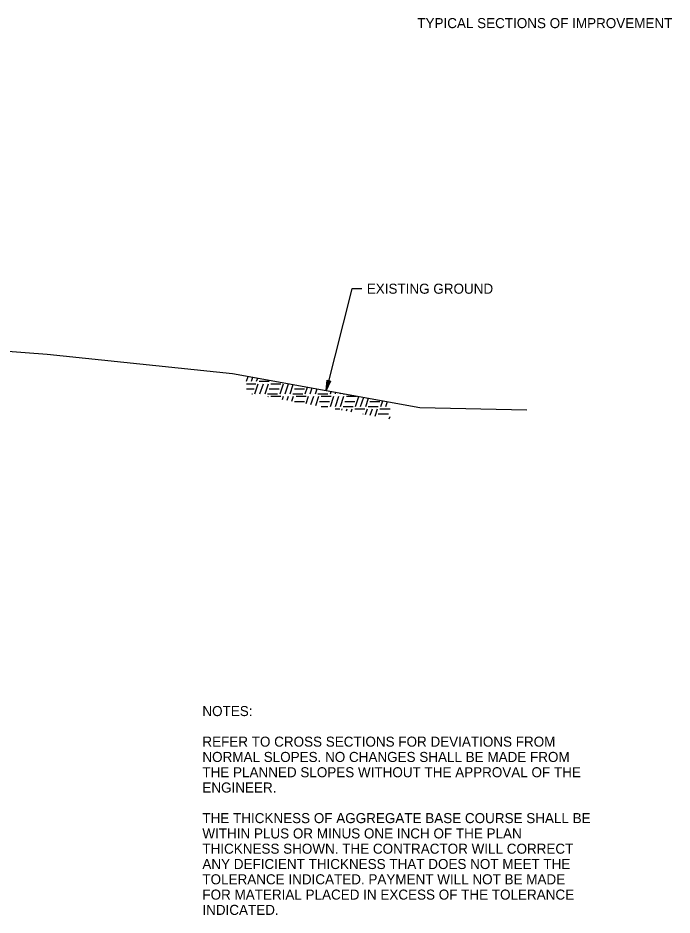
# Model space of a CAD drawing. Extents: x 1824008 to 1828864, y 689441 to 689870.
# Drawn here: x 1828825.4 to 1828864.4, y 689656.7 to 689710.2 of the extents above; entities that cross this region are included whole.
import ezdxf

# ---------------------------------------------------------------- set-up
doc = ezdxf.new("R2010")
doc.units = 0
for name, color, linetype in [('1', 7, 'Continuous'), ('19', 7, 'Continuous'), ('R_Draft', 7, 'Continuous')]:
    doc.layers.add(name, color=color, linetype=linetype)

msp = doc.modelspace()

# ---------------------------------------------------------------- linework, layer by layer
at = {"layer": '1'}
for p, q in [((1828839.043, 689688.541), (1828839.136, 689688.823)), ((1828839.043, 689688.541), (1828839.136, 689688.823)), ((1828839.043, 689688.541), (1828839.136, 689688.823)), ((1828839.34, 689688.532), (1828839.419, 689688.771)), ((1828839.34, 689688.532), (1828839.419, 689688.771)), ((1828839.34, 689688.532), (1828839.419, 689688.771)), ((1828839.64, 689688.532), (1828839.702, 689688.72)), ((1828839.64, 689688.532), (1828839.702, 689688.72)), ((1828839.64, 689688.532), (1828839.702, 689688.72)), ((1828839.043, 689688.382), (1828839.54, 689688.382)), ((1828839.043, 689688.382), (1828839.54, 689688.382)), ((1828839.043, 689688.382), (1828839.54, 689688.382)), ((1828839.043, 689688.082), (1828839.49, 689688.082)), ((1828839.043, 689688.082), (1828839.49, 689688.082)), ((1828839.043, 689688.082), (1828839.49, 689688.082)), ((1828839.54, 689687.782), (1828839.74, 689688.382)), ((1828839.54, 689688.382), (1828839.59, 689688.382)), ((1828839.54, 689687.782), (1828839.74, 689688.382)), ((1828839.54, 689688.382), (1828839.59, 689688.382)), ((1828839.54, 689687.782), (1828839.74, 689688.382)), ((1828839.54, 689688.382), (1828839.59, 689688.382)), ((1828839.79, 689688.532), (1828840.39, 689688.532)), ((1828839.79, 689688.532), (1828840.39, 689688.532)), ((1828839.79, 689688.532), (1828840.39, 689688.532)), ((1828839.84, 689687.782), (1828840.04, 689688.382)), ((1828839.84, 689687.782), (1828840.04, 689688.382)), ((1828839.84, 689687.782), (1828840.04, 689688.382)), ((1828840.14, 689687.782), (1828840.34, 689688.382)), ((1828840.14, 689687.782), (1828840.34, 689688.382)), ((1828840.14, 689687.782), (1828840.34, 689688.382)), ((1828840.39, 689688.082), (1828840.99, 689688.082)), ((1828840.39, 689688.082), (1828840.99, 689688.082)), ((1828840.39, 689688.082), (1828840.99, 689688.082)), ((1828840.49, 689688.382), (1828841.09, 689688.382)), ((1828840.49, 689688.382), (1828841.09, 689688.382)), ((1828840.49, 689688.382), (1828841.09, 689688.382)), ((1828840.54, 689688.532), (1828840.551, 689688.566)), ((1828840.54, 689688.532), (1828840.551, 689688.566)), ((1828840.54, 689688.532), (1828840.551, 689688.566)), ((1828841.04, 689687.782), (1828841.24, 689688.382)), ((1828841.04, 689687.782), (1828841.24, 689688.382)), ((1828841.04, 689687.782), (1828841.24, 689688.382)), ((1828841.34, 689687.782), (1828841.54, 689688.382)), ((1828841.34, 689687.782), (1828841.54, 689688.382)), ((1828841.34, 689687.782), (1828841.54, 689688.382)), ((1828841.64, 689687.782), (1828841.824, 689688.335)), ((1828841.64, 689687.782), (1828841.824, 689688.335)), ((1828841.64, 689687.782), (1828841.824, 689688.335)), ((1828841.89, 689688.082), (1828842.49, 689688.082)), ((1828841.89, 689688.082), (1828842.49, 689688.082)), ((1828841.89, 689688.082), (1828842.49, 689688.082)), ((1828842.54, 689687.782), (1828842.673, 689688.181)), ((1828842.54, 689687.782), (1828842.673, 689688.181)), ((1828842.54, 689687.782), (1828842.673, 689688.181)), ((1828842.84, 689687.782), (1828842.956, 689688.13)), ((1828842.84, 689687.782), (1828842.956, 689688.13)), ((1828842.84, 689687.782), (1828842.956, 689688.13)), ((1828843.14, 689687.782), (1828843.238, 689688.079)), ((1828843.14, 689687.782), (1828843.238, 689688.079)), ((1828843.14, 689687.782), (1828843.238, 689688.079)), ((1828843.792, 689687.978), (1828843.835, 689688.586)), ((1828844.038, 689688.535), (1828843.792, 689687.978)), ((1828843.82, 689688.135), (1828843.886, 689688.568)), ((1828843.835, 689688.586), (1828844.038, 689688.535)), ((1828843.992, 689688.543), (1828843.845, 689688.131)), ((1828839.357, 689687.782), (1828839.39, 689687.782)), ((1828839.357, 689687.782), (1828839.39, 689687.782)), ((1828839.357, 689687.782), (1828839.39, 689687.782)), ((1828840.29, 689687.782), (1828840.89, 689687.782)), ((1828840.29, 689687.782), (1828840.89, 689687.782)), ((1828840.29, 689687.782), (1828840.89, 689687.782)), ((1828840.331, 689687.606), (1828840.34, 689687.632)), ((1828840.331, 689687.606), (1828840.34, 689687.632)), ((1828840.331, 689687.606), (1828840.34, 689687.632)), ((1828840.49, 689687.632), (1828841.09, 689687.632)), ((1828840.49, 689687.632), (1828841.09, 689687.632)), ((1828840.49, 689687.632), (1828841.09, 689687.632)), ((1828841.18, 689687.452), (1828841.24, 689687.632)), ((1828841.18, 689687.452), (1828841.24, 689687.632)), ((1828841.18, 689687.452), (1828841.24, 689687.632)), ((1828841.462, 689687.401), (1828841.54, 689687.632)), ((1828841.462, 689687.401), (1828841.54, 689687.632)), ((1828841.462, 689687.401), (1828841.54, 689687.632)), ((1828841.745, 689687.35), (1828841.84, 689687.632)), ((1828841.745, 689687.35), (1828841.84, 689687.632)), ((1828841.745, 689687.35), (1828841.84, 689687.632)), ((1828841.79, 689687.782), (1828842.39, 689687.782)), ((1828841.79, 689687.782), (1828842.39, 689687.782)), ((1828841.79, 689687.782), (1828842.39, 689687.782)), ((1828841.99, 689687.632), (1828842.54, 689687.632)), ((1828841.99, 689687.632), (1828842.54, 689687.632)), ((1828841.99, 689687.632), (1828842.54, 689687.632)), ((1828842.54, 689687.632), (1828842.59, 689687.632)), ((1828842.54, 689687.632), (1828842.59, 689687.632)), ((1828842.54, 689687.632), (1828842.59, 689687.632)), ((1828842.594, 689687.196), (1828842.74, 689687.632)), ((1828842.594, 689687.196), (1828842.74, 689687.632)), ((1828842.594, 689687.196), (1828842.74, 689687.632)), ((1828842.877, 689687.144), (1828843.04, 689687.632)), ((1828842.877, 689687.144), (1828843.04, 689687.632)), ((1828842.877, 689687.144), (1828843.04, 689687.632)), ((1828843.16, 689687.093), (1828843.34, 689687.632)), ((1828843.16, 689687.093), (1828843.34, 689687.632)), ((1828843.16, 689687.093), (1828843.34, 689687.632)), ((1828843.29, 689687.782), (1828843.89, 689687.782)), ((1828843.29, 689687.782), (1828843.89, 689687.782)), ((1828843.29, 689687.782), (1828843.89, 689687.782)), ((1828843.49, 689687.632), (1828844.09, 689687.632)), ((1828843.49, 689687.632), (1828844.09, 689687.632)), ((1828843.49, 689687.632), (1828844.09, 689687.632)), ((1828844.04, 689687.782), (1828844.087, 689687.925)), ((1828844.04, 689687.782), (1828844.087, 689687.925)), ((1828844.04, 689687.782), (1828844.087, 689687.925)), ((1828844.04, 689687.032), (1828844.24, 689687.632)), ((1828844.04, 689687.032), (1828844.24, 689687.632)), ((1828844.04, 689687.032), (1828844.24, 689687.632)), ((1828844.34, 689687.782), (1828844.37, 689687.874)), ((1828844.34, 689687.782), (1828844.37, 689687.874)), ((1828844.34, 689687.782), (1828844.37, 689687.874)), ((1828844.34, 689687.032), (1828844.54, 689687.632)), ((1828844.34, 689687.032), (1828844.54, 689687.632)), ((1828844.34, 689687.032), (1828844.54, 689687.632)), ((1828844.64, 689687.782), (1828844.653, 689687.822)), ((1828844.64, 689687.782), (1828844.653, 689687.822)), ((1828844.64, 689687.782), (1828844.653, 689687.822)), ((1828844.64, 689687.032), (1828844.84, 689687.632)), ((1828844.64, 689687.032), (1828844.84, 689687.632)), ((1828844.64, 689687.032), (1828844.84, 689687.632)), ((1828844.79, 689687.782), (1828844.872, 689687.782)), ((1828844.79, 689687.782), (1828844.872, 689687.782)), ((1828844.79, 689687.782), (1828844.872, 689687.782)), ((1828844.99, 689687.632), (1828845.54, 689687.632)), ((1828844.99, 689687.632), (1828845.54, 689687.632)), ((1828844.99, 689687.632), (1828845.54, 689687.632)), ((1828845.54, 689687.632), (1828845.59, 689687.632)), ((1828845.54, 689687.632), (1828845.59, 689687.632)), ((1828845.54, 689687.632), (1828845.59, 689687.632)), ((1828845.54, 689687.032), (1828845.737, 689687.626)), ((1828845.54, 689687.032), (1828845.737, 689687.626)), ((1828845.54, 689687.032), (1828845.737, 689687.626)), ((1828845.84, 689687.032), (1828846.02, 689687.574)), ((1828845.84, 689687.032), (1828846.02, 689687.574)), ((1828845.84, 689687.032), (1828846.02, 689687.574)), ((1828841.89, 689687.332), (1828842.49, 689687.332)), ((1828841.89, 689687.332), (1828842.49, 689687.332)), ((1828841.89, 689687.332), (1828842.49, 689687.332)), ((1828843.39, 689687.332), (1828843.99, 689687.332)), ((1828843.39, 689687.332), (1828843.99, 689687.332)), ((1828843.39, 689687.332), (1828843.99, 689687.332)), ((1828843.494, 689687.032), (1828843.89, 689687.032)), ((1828843.494, 689687.032), (1828843.89, 689687.032)), ((1828843.494, 689687.032), (1828843.89, 689687.032)), ((1828844.79, 689687.032), (1828845.39, 689687.032)), ((1828844.79, 689687.032), (1828845.39, 689687.032)), ((1828844.79, 689687.032), (1828845.39, 689687.032)), ((1828844.89, 689687.332), (1828845.49, 689687.332)), ((1828844.89, 689687.332), (1828845.49, 689687.332)), ((1828844.89, 689687.332), (1828845.49, 689687.332)), ((1828846.14, 689687.032), (1828846.303, 689687.523)), ((1828846.14, 689687.032), (1828846.303, 689687.523)), ((1828846.14, 689687.032), (1828846.303, 689687.523)), ((1828846.29, 689687.032), (1828846.89, 689687.032)), ((1828846.29, 689687.032), (1828846.89, 689687.032)), ((1828846.29, 689687.032), (1828846.89, 689687.032)), ((1828846.39, 689687.332), (1828846.99, 689687.332)), ((1828846.39, 689687.332), (1828846.99, 689687.332)), ((1828846.39, 689687.332), (1828846.99, 689687.332)), ((1828847.04, 689687.032), (1828847.152, 689687.369)), ((1828847.04, 689687.032), (1828847.152, 689687.369)), ((1828847.04, 689687.032), (1828847.152, 689687.369)), ((1828847.34, 689687.032), (1828847.435, 689687.318)), ((1828847.34, 689687.032), (1828847.435, 689687.318)), ((1828847.34, 689687.032), (1828847.435, 689687.318)), ((1828844.321, 689686.882), (1828844.59, 689686.882)), ((1828844.321, 689686.882), (1828844.59, 689686.882)), ((1828844.321, 689686.882), (1828844.59, 689686.882)), ((1828844.716, 689686.811), (1828844.74, 689686.882)), ((1828844.716, 689686.811), (1828844.74, 689686.882)), ((1828844.716, 689686.811), (1828844.74, 689686.882)), ((1828844.999, 689686.76), (1828845.04, 689686.882)), ((1828844.999, 689686.76), (1828845.04, 689686.882)), ((1828844.999, 689686.76), (1828845.04, 689686.882)), ((1828845.282, 689686.708), (1828845.34, 689686.882)), ((1828845.282, 689686.708), (1828845.34, 689686.882)), ((1828845.282, 689686.708), (1828845.34, 689686.882)), ((1828845.49, 689686.882), (1828845.54, 689686.882)), ((1828845.49, 689686.882), (1828845.54, 689686.882)), ((1828845.49, 689686.882), (1828845.54, 689686.882)), ((1828845.54, 689686.882), (1828846.09, 689686.882)), ((1828845.54, 689686.882), (1828846.09, 689686.882)), ((1828845.54, 689686.882), (1828846.09, 689686.882)), ((1828845.975, 689686.582), (1828845.99, 689686.582)), ((1828845.975, 689686.582), (1828845.99, 689686.582)), ((1828845.975, 689686.582), (1828845.99, 689686.582)), ((1828846.13, 689686.554), (1828846.24, 689686.882)), ((1828846.13, 689686.554), (1828846.24, 689686.882)), ((1828846.13, 689686.554), (1828846.24, 689686.882)), ((1828846.413, 689686.503), (1828846.54, 689686.882)), ((1828846.413, 689686.503), (1828846.54, 689686.882)), ((1828846.413, 689686.503), (1828846.54, 689686.882)), ((1828846.696, 689686.452), (1828846.84, 689686.882)), ((1828846.696, 689686.452), (1828846.84, 689686.882)), ((1828846.696, 689686.452), (1828846.84, 689686.882)), ((1828846.89, 689686.582), (1828847.49, 689686.582)), ((1828846.89, 689686.582), (1828847.49, 689686.582)), ((1828846.89, 689686.582), (1828847.49, 689686.582)), ((1828846.99, 689686.882), (1828847.589, 689686.882)), ((1828846.99, 689686.882), (1828847.589, 689686.882)), ((1828846.99, 689686.882), (1828847.589, 689686.882)), ((1828847.545, 689686.298), (1828847.589, 689686.43)), ((1828847.545, 689686.298), (1828847.589, 689686.43)), ((1828847.545, 689686.298), (1828847.589, 689686.43))]:
    msp.add_line(p, q, dxfattribs=at)
for points in [[(1828845.904, 689694.052), (1828845.304, 689694.051), (1828843.792, 689687.978)], [(1828815.101, 689691.061), (1828827.154, 689690.152), (1828838.209, 689688.991), (1828849.374, 689686.966), (1828855.735, 689686.83)]]:
    msp.add_lwpolyline(points, dxfattribs=at)
at = {"layer": 'R_Draft'}
for p, q in [((1828839.043, 689688.541), (1828839.136, 689688.823)), ((1828839.34, 689688.532), (1828839.419, 689688.771)), ((1828839.64, 689688.532), (1828839.702, 689688.72)), ((1828839.043, 689688.382), (1828839.54, 689688.382)), ((1828839.043, 689688.082), (1828839.49, 689688.082)), ((1828839.54, 689687.782), (1828839.74, 689688.382)), ((1828839.54, 689688.382), (1828839.59, 689688.382)), ((1828839.79, 689688.532), (1828840.39, 689688.532)), ((1828839.84, 689687.782), (1828840.04, 689688.382)), ((1828840.14, 689687.782), (1828840.34, 689688.382)), ((1828840.39, 689688.082), (1828840.99, 689688.082)), ((1828840.49, 689688.382), (1828841.09, 689688.382)), ((1828840.54, 689688.532), (1828840.551, 689688.566)), ((1828841.04, 689687.782), (1828841.24, 689688.382)), ((1828841.34, 689687.782), (1828841.54, 689688.382)), ((1828841.64, 689687.782), (1828841.824, 689688.335)), ((1828841.89, 689688.082), (1828842.49, 689688.082)), ((1828842.54, 689687.782), (1828842.673, 689688.181)), ((1828842.84, 689687.782), (1828842.956, 689688.13)), ((1828843.14, 689687.782), (1828843.238, 689688.079)), ((1828839.357, 689687.782), (1828839.39, 689687.782)), ((1828840.29, 689687.782), (1828840.89, 689687.782)), ((1828840.331, 689687.606), (1828840.34, 689687.632)), ((1828840.49, 689687.632), (1828841.09, 689687.632)), ((1828841.18, 689687.452), (1828841.24, 689687.632)), ((1828841.462, 689687.401), (1828841.54, 689687.632)), ((1828841.745, 689687.35), (1828841.84, 689687.632)), ((1828841.79, 689687.782), (1828842.39, 689687.782)), ((1828841.99, 689687.632), (1828842.54, 689687.632)), ((1828842.54, 689687.632), (1828842.59, 689687.632)), ((1828842.594, 689687.196), (1828842.74, 689687.632)), ((1828842.877, 689687.144), (1828843.04, 689687.632)), ((1828843.16, 689687.093), (1828843.34, 689687.632)), ((1828843.29, 689687.782), (1828843.89, 689687.782)), ((1828843.49, 689687.632), (1828844.09, 689687.632)), ((1828844.04, 689687.782), (1828844.087, 689687.925)), ((1828844.04, 689687.032), (1828844.24, 689687.632)), ((1828844.34, 689687.782), (1828844.37, 689687.874)), ((1828844.34, 689687.032), (1828844.54, 689687.632)), ((1828844.64, 689687.782), (1828844.653, 689687.822)), ((1828844.64, 689687.032), (1828844.84, 689687.632)), ((1828844.79, 689687.782), (1828844.872, 689687.782)), ((1828844.99, 689687.632), (1828845.54, 689687.632)), ((1828845.54, 689687.632), (1828845.59, 689687.632)), ((1828845.54, 689687.032), (1828845.737, 689687.626)), ((1828845.84, 689687.032), (1828846.02, 689687.574)), ((1828841.89, 689687.332), (1828842.49, 689687.332)), ((1828843.39, 689687.332), (1828843.99, 689687.332)), ((1828843.494, 689687.032), (1828843.89, 689687.032)), ((1828844.79, 689687.032), (1828845.39, 689687.032)), ((1828844.89, 689687.332), (1828845.49, 689687.332)), ((1828846.14, 689687.032), (1828846.303, 689687.523)), ((1828846.29, 689687.032), (1828846.89, 689687.032)), ((1828846.39, 689687.332), (1828846.99, 689687.332)), ((1828847.04, 689687.032), (1828847.152, 689687.369)), ((1828847.34, 689687.032), (1828847.435, 689687.318)), ((1828844.321, 689686.882), (1828844.59, 689686.882)), ((1828844.716, 689686.811), (1828844.74, 689686.882)), ((1828844.999, 689686.76), (1828845.04, 689686.882)), ((1828845.282, 689686.708), (1828845.34, 689686.882)), ((1828845.49, 689686.882), (1828845.54, 689686.882)), ((1828845.54, 689686.882), (1828846.09, 689686.882)), ((1828845.975, 689686.582), (1828845.99, 689686.582)), ((1828846.13, 689686.554), (1828846.24, 689686.882)), ((1828846.413, 689686.503), (1828846.54, 689686.882)), ((1828846.696, 689686.452), (1828846.84, 689686.882)), ((1828846.89, 689686.582), (1828847.49, 689686.582)), ((1828846.99, 689686.882), (1828847.589, 689686.882)), ((1828847.545, 689686.298), (1828847.589, 689686.43))]:
    msp.add_line(p, q, dxfattribs=at)

# ---------------------------------------------------------------- texts
at = {"layer": '19'}
for s, p in [('NOTES:', (1828836.406, 689668.554)), ('REFER TO CROSS SECTIONS FOR DEVIATIONS FROM', (1828836.406, 689666.729)), ('NORMAL SLOPES. NO CHANGES SHALL BE MADE FROM ', (1828836.406, 689665.817)), ('THE PLANNED SLOPES WITHOUT THE APPROVAL OF THE', (1828836.406, 689664.904)), ('ENGINEER.', (1828836.406, 689663.992)), ('THE THICKNESS OF AGGREGATE BASE COURSE SHALL BE', (1828836.406, 689662.167)), ('WITHIN PLUS OR MINUS ONE INCH OF THE PLAN ', (1828836.406, 689661.254)), ('THICKNESS SHOWN. THE CONTRACTOR WILL CORRECT', (1828836.406, 689660.342)), ('ANY DEFICIENT THICKNESS THAT DOES NOT MEET THE', (1828836.406, 689659.429)), ('TOLERANCE INDICATED. PAYMENT WILL NOT BE MADE', (1828836.406, 689658.517)), ('FOR MATERIAL PLACED IN EXCESS OF THE TOLERANCE', (1828836.406, 689657.604)), ('INDICATED.', (1828836.406, 689656.692))]:
    msp.add_text(s, height=0.6, dxfattribs=at).set_placement(p)
at = {"layer": 'R_Draft'}
for s, p in [('TYPICAL SECTIONS OF IMPROVEMENT', (1828849.216, 689709.598)), ('EXISTING GROUND', (1828846.204, 689693.752))]:
    msp.add_text(s, height=0.6, dxfattribs=at).set_placement(p)

doc.saveas('drawing.dxf')
